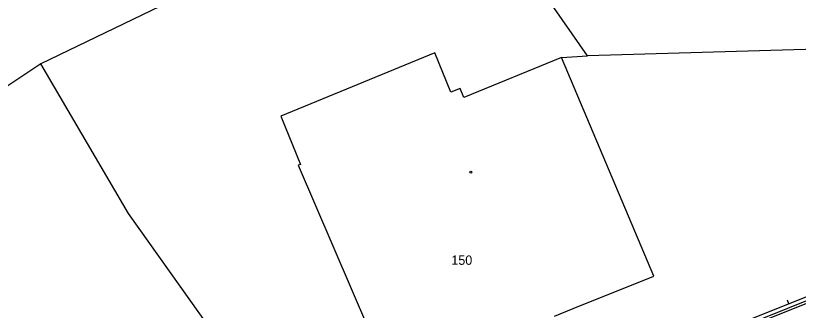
# Model space of a CAD drawing. Extents: x -711081 to -709338, y -1025122 to -1024092.
# Drawn here: x -709877.47 to -709841.94, y -1024542.23 to -1024528.84 of the extents above; entities that cross this region are included whole.
import ezdxf

# ---------------------------------------------------------------- set-up
doc = ezdxf.new("R2010")
doc.units = 0
for name, color, linetype in [('Z_katastr_cisla_stavebni', 7, 'Continuous'), ('Z_katastr_hranice', 7, 'Continuous'), ('Z_katastr_vnitrni_kresba', 7, 'Continuous'), ('Z_katastr_znacky_budov', 7, 'Continuous'), ('Z_ploty', 7, 'Continuous'), ('Z_ploty_znacky', 7, 'Continuous')]:
    doc.layers.add(name, color=color, linetype=linetype)

# ---------------------------------------------------------------- blocks, each defined once
blk = doc.blocks.new('Z210')
blk.add_line((0, 0), (0, 0.17))

msp = doc.modelspace()

# ---------------------------------------------------------------- linework, layer by layer
at = {"layer": 'Z_katastr_hranice'}
for p, q in [((-709860.81, -1024523.53), (-709876.32, -1024531.02)), ((-709851.52, -1024530.66), (-709856.58, -1024523.37)), ((-709816.92, -1024529.68), (-709851.52, -1024530.66)), ((-709852.7, -1024530.74), (-709851.52, -1024530.66)), ((-709848.5, -1024540.67), (-709852.7, -1024530.74)), ((-709876.32, -1024531.02), (-709879.52, -1024533.13)), ((-709872.34, -1024537.83), (-709876.32, -1024531.02)), ((-709851.53, -1024545.9), (-709816.1, -1024531.67)), ((-709863.27, -1024550.61), (-709872.34, -1024537.83)), ((-709852.16, -1024542.15), (-709848.5, -1024540.67)), ((-709853.01, -1024542.49), (-709852.16, -1024542.15))]:
    msp.add_line(p, q, dxfattribs=at)
at = {"layer": 'Z_katastr_vnitrni_kresba'}
for p, q in [((-709858.44, -1024530.53), (-709865.44, -1024533.4)), ((-709857.71, -1024532.32), (-709858.44, -1024530.53)), ((-709852.7, -1024530.74), (-709857.13, -1024532.56)), ((-709857.3, -1024532.15), (-709857.71, -1024532.32)), ((-709857.13, -1024532.56), (-709857.3, -1024532.15)), ((-709865.44, -1024533.4), (-709864.54, -1024535.6)), ((-709864.54, -1024535.6), (-709864.64, -1024535.63)), ((-709864.64, -1024535.63), (-709860.42, -1024545.49))]:
    msp.add_line(p, q, dxfattribs=at)
at = {"layer": 'Z_katastr_znacky_budov'}
msp.add_circle((-709856.812, -1024535.95), 0.0437, dxfattribs=at)
at = {"layer": 'Z_ploty'}
for p, q in [((-709845.86, -1024543.32), (-709838.08, -1024540.21)), ((-709845.8, -1024543.48), (-709838.02, -1024540.37))]:
    msp.add_line(p, q, dxfattribs=at)

# ---------------------------------------------------------------- block references
at = {"layer": 'Z_ploty_znacky', "rotation": 21.8}
msp.add_blockref('Z210', (-709842.38, -1024541.93), dxfattribs=at)

# ---------------------------------------------------------------- texts
at = {"layer": 'Z_katastr_cisla_stavebni'}
msp.add_text('150', height=0.425, dxfattribs=at).set_placement((-709857.694, -1024540.16))

doc.saveas('drawing.dxf')
